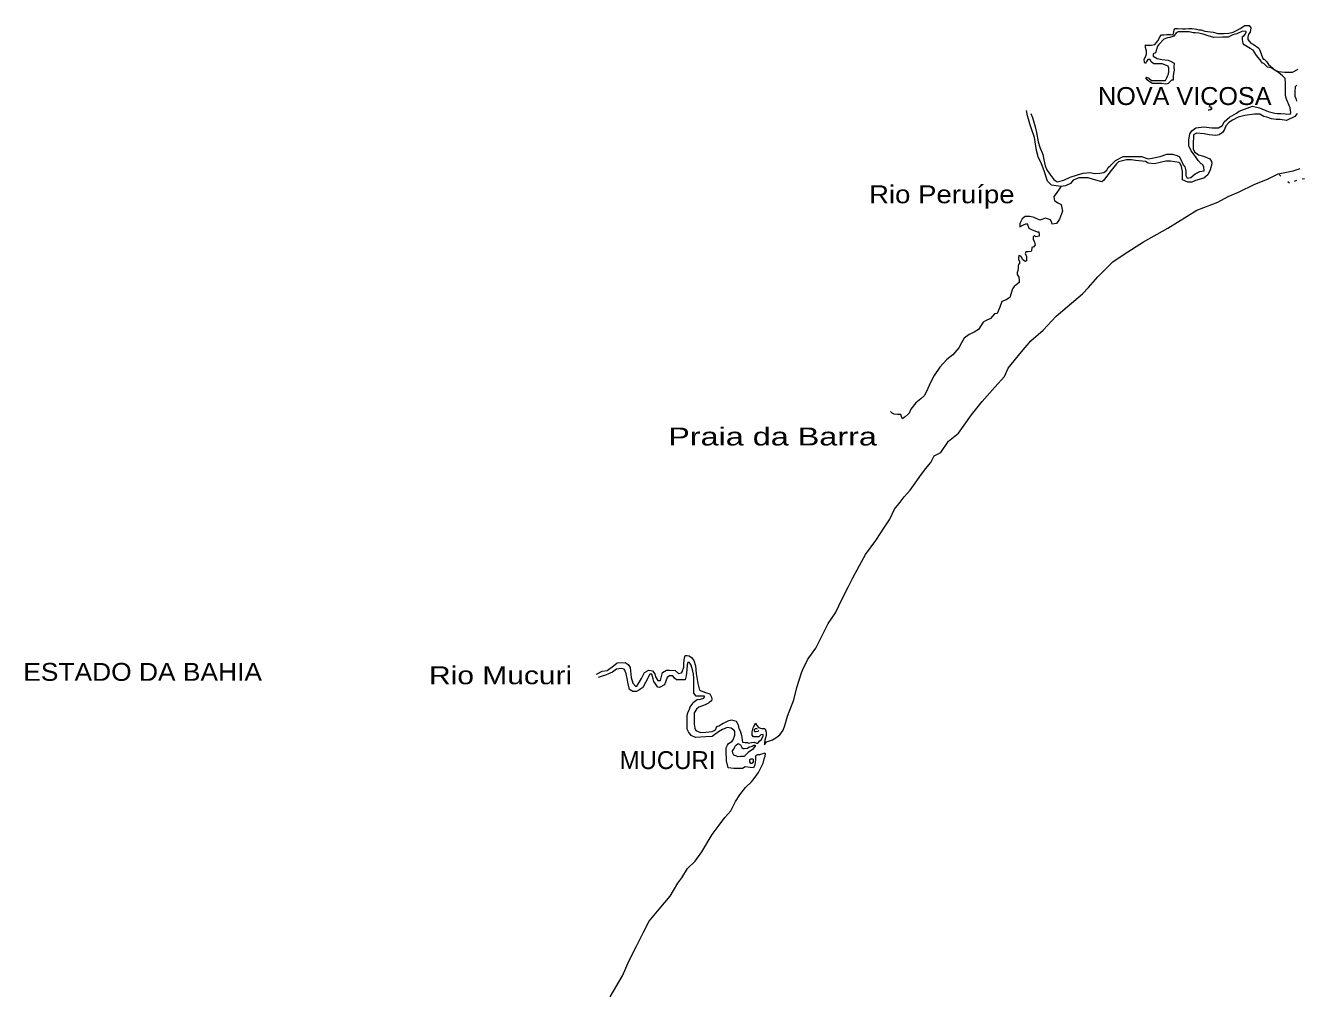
# Model space of a CAD drawing. Extents: x 47169 to 972804, y 7447977 to 9608469.
# Drawn here: x 414694 to 460779, y 7990522 to 8025478 of the extents above; entities that cross this region are included whole.
import ezdxf

# ---------------------------------------------------------------- set-up
doc = ezdxf.new("R2010")
doc.units = 0
doc.header["$LTSCALE"] = 270
doc.linetypes.add('DOTTED', pattern=[1.5, 0.3, -1.2])
doc.layers.add('1', color=7, linetype='Continuous', lineweight=13)
doc.layers.add('3', color=7, linetype='Continuous')

msp = doc.modelspace()

# ---------------------------------------------------------------- linework, layer by layer
at = {"layer": '1'}
for points in [[(456210.3, 8025144.1), (456302.5, 8025136.6), (456333, 8025245.1), (456341.3, 8025321.4), (456371.9, 8025360.2), (456464.1, 8025368.2), (456641, 8025359.7), (456748, 8025352.2), (456870.9, 8025368), (456993.9, 8025360.5), (457147.5, 8025337.6), (457232.3, 8025322.3), (457324.5, 8025322.5), (457447.5, 8025268.5), (457755.9, 8025238.2), (457931.9, 8025184.4), (458155.5, 8025184.9), (458323.9, 8025191.8), (458478.5, 8025230.9), (458623.5, 8025307.5), (458731.5, 8025362), (458900.8, 8025477.4), (458915.6, 8025477.4), (459061.8, 8025477.7), (459116, 8025384.9), (459093, 8025238.8), (459031.7, 8025162.3), (459016.1, 8025055), (459008.9, 8024962), (459124.6, 8024839.5), (459208.4, 8024793.2), (459416.3, 8024655.3), (459463.2, 8024539.2), (459547.4, 8024309.3), (459570.8, 8024255.1), (459601.5, 8024255.2), (459693.9, 8024170.2), (459763, 8024055.2)], [(459594.4, 8024093.6), (459540.4, 8024109), (459462.8, 8024231.6), (459324.7, 8024392.9), (459201.4, 8024577.4), (459093.2, 8024646.9), (458877.9, 8024770.4), (458839.6, 8024823.4), (458817.1, 8024969.4), (458824.3, 8025077.8), (458878.2, 8025115.5), (458923.6, 8025177.6), (458946.8, 8025231.9), (458946.8, 8025261.7), (458823.9, 8025269.2), (458609, 8025169.2), (458462.8, 8025131.3), (458302, 8025053.5), (458094.3, 8025054.2), (457778.6, 8025038), (457579.3, 8025099.5), (457386.3, 8025161.1), (457240, 8025191.7), (457102.2, 8025206.9), (457024.9, 8025214.5), (456887.1, 8025245.2), (456755.7, 8025244.9), (456602.1, 8025244.6), (456486.6, 8025244.3), (456417.8, 8025206.5), (456333.3, 8025083.5), (456187.2, 8025036.8), (456095, 8025028.8), (455964.8, 8024975.4), (455788.3, 8024790.2), (455734.4, 8024721.5), (455666.1, 8024482.4), (455581.4, 8024451.2), (455581.6, 8024367.1), (455728, 8024274.5), (455889.1, 8024243.9), (456119.1, 8024213.5), (456234.7, 8024175), (456335.5, 8024114.4), (456334.7, 8023968.3), (456335, 8023852.1), (456313, 8023729.3), (456304.7, 8023652.9), (456304.9, 8023567.7), (456305, 8023491.4), (456243.6, 8023491.2), (456151.6, 8023398.1), (456128.4, 8023368.2), (456036.2, 8023352.5), (455882.6, 8023367.6), (455721.6, 8023367.3), (455651.7, 8023367.1), (455544.7, 8023366.9), (455490.5, 8023413.2), (455429, 8023444.1), (455367.4, 8023505.9), (455313.2, 8023582.1), (455336.5, 8023605.4), (455421.3, 8023566.9), (455521.1, 8023483), (455598.4, 8023482.1), (455698, 8023482.3), (455844.2, 8023482.6), (456028.5, 8023483), (456073.9, 8023575), (456097.1, 8023637), (456136.1, 8023713.4), (456143.3, 8023821.8), (456150.5, 8023929.2), (456119.5, 8024006.5), (455904.3, 8024082.4), (455720, 8024083.1), (455604.5, 8024082.9), (455512.1, 8024159), (455489.8, 8024205.4), (455450.5, 8024236.3), (455389, 8024243.9), (455343.7, 8024166.4), (455297.2, 8024097.7), (455266.4, 8024136.3), (455251.3, 8024259.1), (455327.3, 8024389.8), (455335.6, 8024451.8), (455335.4, 8024543.6), (455304.4, 8024674.1), (455296.7, 8024774.8), (455334.9, 8024767.1), (455511.8, 8024766.4), (455642.1, 8024789.9), (455757.3, 8024936.2), (455818.4, 8025059.2), (455879.7, 8025136.8), (455964.5, 8025137), (456080, 8025143.8), (456148.8, 8025144), (456210.3, 8025144.1)], [(460088.6, 8022286.8), (460096, 8022286.8), (460211.5, 8022279.3), (460372.5, 8022271.9), (460549.5, 8022263.4), (460572.7, 8022317.6), (460541.6, 8022494.6), (460410.7, 8022809.6), (460379.7, 8022932.4), (460371.3, 8023401.5), (460363.6, 8023555.3), (460263.8, 8023648), (460124.8, 8023770.5), (459855.4, 8023940.4), (459725, 8023963.3), (459594.4, 8024093.6)], [(459763, 8024055.2), (460001.7, 8023855.5), (460124.7, 8023801.5), (460355.8, 8023778.7), (460540.1, 8023779.1), (460632.2, 8023779.3), (460832.3, 8023887)], [(460786.8, 8023309.4), (460725.5, 8023248.4), (460717.3, 8023086.9), (460717.7, 8022909.8), (460748.6, 8022833.5), (460779.5, 8022732.9)], [(451142.2, 8022285.5), (451204, 8022139.6), (451250, 8021970.4), (451304.4, 8021801.3), (451350.5, 8021593.4), (451412.7, 8021262.7), (451474.7, 8021063.7), (451582.3, 8020794), (451620.9, 8020609.4), (451668, 8020387.1), (451721.4, 8020240.1), (451829.8, 8020086.5), (451983.9, 8019886.7), (452099.5, 8019810.6), (452345.1, 8019864.3), (452567.3, 8019972.2), (452836.2, 8020056.9), (453036.2, 8020119.3), (453289.3, 8020149.8), (453458.9, 8020111.5), (453650.6, 8020119.7), (453789.3, 8020151), (453897.1, 8020235.3), (453942.5, 8020327.2), (454019.7, 8020381.7), (454219.4, 8020581.3), (454488.1, 8020720.2), (454772, 8020728.6), (455064.4, 8020728.1), (455156.5, 8020728.4), (455402.5, 8020644.8), (455548.6, 8020659.5), (455832.4, 8020722.1), (456070.5, 8020806.8), (456278.1, 8020815), (456439.2, 8020761.1), (456524.1, 8020722.6), (456585.8, 8020614.3), (456670.9, 8020423), (456725.1, 8020345.7), (456763.5, 8020207.5), (456763.9, 8020038.2), (456817.1, 8019945.4), (456948.4, 8019961.2), (457101.7, 8020092.1), (457271, 8020176.5), (457424.5, 8020207.8), (457416.8, 8020346.1), (457362.6, 8020431.2), (457315.9, 8020462.1), (457216.1, 8020584.7), (457116.2, 8020730.5), (456962.2, 8020930.4), (456877, 8021115), (456876.6, 8021323), (456907.9, 8021553.2), (456983.9, 8021660.7), (457129.9, 8021761.7), (457414.7, 8021799.9), (457706.1, 8021769.6), (457951.9, 8021762.3), (458097.9, 8021854.5), (458159.1, 8021977.4), (458351.5, 8022154.9), (458604.4, 8022292.6), (458697.5, 8022370.2), (459181.2, 8022547.1), (459434.5, 8022493.5), (459750.5, 8022355.8), (459996.4, 8022302.1), (460088.6, 8022286.8)], [(460181.2, 8022071.2), (460035, 8022063.2), (459865.5, 8022093.8), (459696.9, 8022147.7), (459596.2, 8022178.5), (459442.4, 8022263.3), (459250.7, 8022262.9), (458897, 8022216.9), (458666.2, 8022146.7), (458451.3, 8022038.9), (458328.6, 8021962.3), (458213.4, 8021839.2), (458159.7, 8021700.8), (458098.4, 8021600), (457968.3, 8021515.7), (457852.9, 8021492.2), (457614.5, 8021516), (457422.7, 8021546.6), (457153.6, 8021569.2), (457045.7, 8021507), (457030.6, 8021146.3), (457030.9, 8021006.9), (457077.7, 8020891.9), (457223.1, 8020784.9), (457400.1, 8020738.9), (457631.2, 8020638.7), (457700.3, 8020547), (457700.5, 8020454), (457646.9, 8020239.3), (457562.5, 8020062.1), (457416.6, 8019939), (457117, 8019854.2), (456986.9, 8019792), (456833.3, 8019791.7), (456648.8, 8019876.4), (456640.7, 8020176.2), (456609.6, 8020361), (456562.8, 8020475.9), (456517.1, 8020506.8), (456209.9, 8020552.6), (456040.4, 8020552.2), (455832.8, 8020506.4), (455625.3, 8020460.6), (455395.4, 8020483.3), (455303.1, 8020543.9), (454941.8, 8020582.9), (454795.6, 8020605.8), (454618.7, 8020605.4), (454319.1, 8020536.1), (454250.4, 8020458.5), (454058.2, 8020220.2), (453774.1, 8019857.8), (453712.7, 8019812.2), (453412.8, 8019889), (453228.3, 8019950.5), (452890.4, 8019949.7), (452683, 8019865.1), (452583.7, 8019749.8), (452407, 8019664.2), (452230.2, 8019633.9), (451892.2, 8019687.3), (451745.7, 8019825.2), (451629.3, 8020202.2), (451529.1, 8020455.4), (451405.6, 8020717.3), (451352.1, 8020939.5), (451274.6, 8021409.5), (451173.2, 8021724.6), (451103.9, 8021909.2), (451065.4, 8022078.4), (451019.5, 8022201.1), (450988.3, 8022393.5)], [(460802.6, 8022279.4), (460719.1, 8022179.6), (460411.2, 8022033), (460181.2, 8022071.2)], [(457924.8, 8019070.4), (458301.5, 8019270.4), (458669.7, 8019431.6), (459269.7, 8019724.9), (459722.7, 8019909.5), (460114.2, 8020095.1), (460659.5, 8020210.1), (460905.1, 8020294.7)], [(452230.2, 8019633.9), (452199.6, 8019579.6), (452068.8, 8019379), (451984.3, 8019279.2), (451984.5, 8019179.7), (452008, 8019125.5), (452123.6, 8019049.5), (452246.6, 8018987.8), (452292.7, 8018748.9), (452178, 8018448.8), (452071.4, 8018294.8), (451916.8, 8018272.3), (451901.9, 8018325.3), (451856.1, 8018433.6), (451670.6, 8018495.2), (451471.6, 8018417.2), (451271.2, 8018517.4), (451110.1, 8018548), (450933.2, 8018547.5), (450825.4, 8018463.2), (450756.9, 8018324.7), (450749.6, 8018278.2), (450749.8, 8018200.8), (450749.9, 8018170.9), (450849.3, 8018239.8), (450987.9, 8018302), (451041, 8018240.2), (451072, 8018125.2), (451164.2, 8018079), (451372, 8017994.3), (451433.5, 8017994.5), (451449.6, 8017887.2), (451449.8, 8017840.7), (451325.9, 8017817.2), (451272.8, 8017863.5), (451226.3, 8017816.9), (451234, 8017725.1), (451280.8, 8017624.5), (451295.9, 8017517.3), (451258, 8017448.6), (451180.7, 8017425.2), (451173.6, 8017302.3), (451157.8, 8017279), (451043.4, 8017263.3), (450958.7, 8017263.1), (450935.5, 8017202.2), (450981.3, 8017109.3), (450981.7, 8016947.8), (450936.2, 8016916.7), (450843.9, 8016986.2), (450813, 8017063.5), (450782.2, 8017116.6), (450704.8, 8017139.6), (450697.6, 8017055.5), (450697.8, 8016978.1), (450728.6, 8016925), (450728.9, 8016839.9), (450698.2, 8016816.5), (450691, 8016747.9), (450690.1, 8016670.5), (450668, 8016594.1), (450652.4, 8016508.8), (450652.5, 8016448), (450706.8, 8016355.2), (450721.9, 8016232.4), (450722.1, 8016155), (450538.2, 8016016.2), (450484.4, 8015924.2), (450384.6, 8015608.7), (450247.1, 8015524.2), (450093.7, 8015463), (450016.9, 8015262.5), (449925.3, 8015038.8), (449833.2, 8015024.2), (449687.6, 8014846.8), (449503.5, 8014762.2), (449410.5, 8014715.5), (449242.7, 8014454), (449088.4, 8014361.7), (448912.8, 8014276.1), (448727.8, 8014145), (448636.2, 8013968.9), (448537.1, 8013783.9), (448314.3, 8013537.7), (448099.8, 8013367.8), (447846.4, 8013082.8), (447639.7, 8012782.4), (447524.9, 8012552), (447349, 8012181.9), (447272.1, 8012051.2), (447157, 8011935.8), (446973.2, 8011789.3), (446789.5, 8011566.4), (446728.5, 8011420.2), (446697.9, 8011389.1), (446590.2, 8011289.2), (446552.1, 8011258.1), (446490.8, 8011219.2), (446459.9, 8011304.4), (446436.4, 8011366.3), (446313.6, 8011365.9)], [(439764.7, 8000056.8), (439833.4, 8000080.3), (439986.6, 8000180.3), (440047.9, 8000210.4), (440170.4, 8000265), (440293.1, 8000296.4), (440462.5, 8000258.1), (440531.7, 8000118.9), (440562.8, 7999988.5), (440601.2, 7999896.8), (440624.7, 7999819.4), (440655.7, 7999735.4), (440663.3, 7999658), (440679.4, 7999581.7), (440694.5, 7999488.8), (440786.6, 7999481.3), (440871.3, 7999473.8), (440902, 7999458.4), (441017.3, 7999482), (441116.7, 7999490), (441201.5, 7999451.6), (441247, 7999451.7), (441324, 7999543.8), (441370.4, 7999574.9), (441438.8, 7999713.4), (441438.6, 7999775.4), (441354, 7999759.6), (441278, 7999689.7), (441146.8, 7999682.7), (441085.4, 7999682.5), (441047.2, 7999743.2), (441039.4, 7999866), (441077, 8000005.5), (441100.2, 8000058.7), (441168.6, 8000181.7), (441208, 8000097.8), (441277, 8000028.2), (441384, 7999989.9), (441438, 7999990), (441499.3, 7999990.2), (441530.2, 7999943.8), (441553.7, 7999852), (441554.1, 7999729.2), (441500.6, 7999567.5), (441492.5, 7999452.4), (441492.7, 7999390.5), (441562.1, 7999505.8), (441776.8, 7999575), (441899.3, 7999652.8), (442045, 7999752.8), (442159.8, 7999930.2), (442228.1, 8000091.9), (442320.2, 8000429.7), (442549.2, 8001022.3), (442663.2, 8001476.3), (442831, 8002000.1), (442877.2, 8002130.8), (443044.4, 8002477.6), (443098.2, 8002554.1), (443343.8, 8002901.1), (443480.6, 8003170.4), (443794.2, 8003793.1), (444063, 8004178.9), (444299.7, 8004686.3), (444529.1, 8005140.6), (444689.2, 8005448.7), (444927.1, 8005895.2), (445148.3, 8006295.3), (445523.7, 8006803.1), (445845.2, 8007280.8), (446029.7, 8007573.4), (446197, 8007935.7), (446412.3, 8008189.7), (446550.4, 8008381.5), (446764.7, 8008628.8), (447016.8, 8008966.9), (447124.4, 8009121), (447331.1, 8009398.2), (447515.7, 8009636.5), (447645.3, 8009868.1), (447875.8, 8009999.3), (448159.5, 8010399.4), (448527.2, 8010699.1), (448994.5, 8011354.2), (449385, 8011838.8), (449837.9, 8012362.2), (450190.6, 8012754.7), (450328.5, 8013054.9), (450803.5, 8013648), (451140.4, 8014048.3), (451593.7, 8014433.3), (452061.6, 8014934.6), (453020.1, 8015750.1), (453234.6, 8015981.9), (453572.6, 8016358.8), (454116.7, 8016905.6), (454531.2, 8017182), (455230.3, 8017637.2), (456113.5, 8018130.5), (457164.9, 8018784.5), (457924.8, 8019070.4)], [(446313.6, 8011365.9), (446190.7, 8011388.8), (446121.8, 8011419.6), (446051.8, 8011480.3)], [(435398.6, 8001955.9), (435605.7, 8002063.9), (435789.8, 8002087.8), (436012.5, 8002256.7), (436142.3, 8002372.2), (436441.8, 8002380.9), (436541.5, 8002311.5), (436619.1, 8002204.5), (436658.4, 8001835), (436712, 8001634.9), (436812.9, 8001520.2), (436865.8, 8001528.1), (437026.8, 8001805.2), (437141.5, 8002020.3), (437294.7, 8002098.2), (437433.4, 8002075.4), (437509.9, 8001967.2), (437541, 8001860), (437626.1, 8001722), (437718.1, 8001722.3), (437755.8, 8001868.4), (437794.5, 8002014.6), (437931.8, 8002099.1), (438047.1, 8002099.5), (438254.6, 8002092.4), (438370.3, 8001976.6), (438477.1, 8002000.2), (438507.7, 8002039), (438561.1, 8002208.4), (438569.1, 8002362.3), (438591.8, 8002546), (438613.8, 8002631.3), (438683.6, 8002631.5), (438752.4, 8002624), (438844.7, 8002562.3), (438929.7, 8002447.5), (438991.7, 8002262.9), (439014.8, 8001978.6), (439069.9, 8001624.7), (439132, 8001378.2), (439354.5, 8001293.7), (439500.7, 8001241), (439569.9, 8001125.1), (439584.9, 8001056.5), (439562.9, 8000994.5), (439478.4, 8000925.6), (439462.6, 8000910.1), (439363.3, 8000863.3), (439271.4, 8000817.7), (439109.6, 8000755.2), (439026.2, 8000694.1), (438933.5, 8000555.5), (438933.9, 8000439.3), (438934.8, 8000147.2), (438966, 8000001.2), (438996.9, 7999909.5), (439165.4, 7999840.3), (439358, 7999848.7), (439596, 7999879.3), (439711.1, 7999933.9), (439764.7, 8000056.8)], [(439818.2, 7999872.2), (439588.1, 7999694.5), (439358.5, 7999679.4), (438990.3, 7999662.8), (438828.2, 7999732), (438728.3, 7999862.2), (438682.5, 7999962.7), (438681.9, 8000146.4), (438680.9, 8000469.5), (438711.3, 8000554.8), (438772.2, 8000693.3), (438787.9, 8000777.4), (438849, 8000847.3), (438902.7, 8000931.6), (439048.4, 8001039.4), (439162.7, 8001047.5), (439285.3, 8001086.6), (439308.4, 8001147.5), (439316.9, 8001163), (439116.9, 8001155.7), (439008.9, 8001155.4), (438932.4, 8001270.2), (438931.8, 8001455), (438923.3, 8001809), (438915.4, 8001962.8), (438891.8, 8002062.3), (438853.3, 8002192.8), (438829.7, 8002285.6), (438784, 8002354.1), (438768, 8002377.3), (438706.7, 8002377.1), (438683.6, 8002292.9), (438676.8, 8002115.9), (438654.2, 8001900), (438616.5, 8001753.9), (438555.2, 8001747), (438301.2, 8001746.2), (438224.8, 8001808), (438163.2, 8001891.9), (438040.4, 8001899.2), (437963.3, 8001838.1), (437864.7, 8001567.8), (437679.8, 8001475.4), (437626.8, 8001483), (437480.1, 8001690.5), (437449.1, 8001783.4), (437403.1, 8001952.5), (437325.8, 8001952.2), (437173.3, 8001659.7), (437073.4, 8001474.6), (436936.1, 8001382.3), (436844.2, 8001327.8), (436713, 8001327.3), (436590, 8001404.4), (436543.8, 8001604.5), (436512.5, 8001804.7), (436473.9, 8001966.1), (436426.8, 8002104.2), (436396, 8002142.9), (436289, 8002165.8), (436119.8, 8002134.2), (435974.1, 8002034.2), (435836.7, 8001971.8), (435728.9, 8001926), (435598.9, 8001886.9), (435460.4, 8001833.3)], [(435896.4, 7990257.9), (436340.3, 7991020.6), (436583.9, 7991574.6), (436843.5, 7992090), (437103.1, 7992598.7), (437309.1, 7992998.8), (437730.6, 7993506.9), (438074.2, 7993908.5), (438349.9, 7994385.2), (438495.3, 7994570.4), (438701.5, 7994916.3), (438969.4, 7995178.2), (439214.9, 7995517.6), (439596.9, 7996149.5), (439841.4, 7996487.7), (440047.9, 7996764.9), (440270.4, 7997003.5), (440438.7, 7997334.8), (440591.3, 7997580.9), (440797.9, 7997850.4), (441020.5, 7998051.4), (441150.1, 7998228.8), (441272.4, 7998390.7), (441356.5, 7998566.9), (441440.7, 7998736.4), (441479.4, 7998882.6), (441509.7, 7998990), (441524.3, 7999067.5), (441501, 7999090.7), (441470.3, 7999082.8), (441309.6, 7999028.1), (441233.4, 7999029), (441163.7, 7998997.8), (441156.5, 7998935.8), (441156.7, 7998867.2), (441141.4, 7998674.7), (441087.7, 7998567.2), (440965, 7998574.5), (440788.2, 7998597.2), (440688.9, 7998542.7), (440374.7, 7998535.1), (440167.2, 7998565.5), (440112.4, 7998818.7), (440112.1, 7998926), (440104.2, 7999080.9), (440103.9, 7999196), (440103.8, 7999226.9), (440103.6, 7999287.8), (440142.4, 7999388.6), (440180.4, 7999441.8), (440310.3, 7999519.7), (440356.7, 7999572.9), (440417.5, 7999750.2), (440417.2, 7999849.7), (440409.7, 7999872.9), (440386.3, 7999911.6), (440279.2, 8000004.2), (440133.1, 8000019.2), (439964, 7999956.8), (439818.2, 7999872.2)], [(441277.3, 7999913.2), (441246.8, 7999874.4), (441185.4, 7999866.4), (441138.9, 7999866.3), (441131.3, 7999905), (441131.2, 7999959.2), (441138.5, 7999967), (441161.8, 7999990.3), (441192.4, 7999990.4), (441207.3, 7999990.4), (441215.8, 7999959.5)], [(441079.7, 7998781.8), (441025.9, 7998713), (440987.9, 7998712.9), (440957, 7998773.7), (440956.7, 7998851.1), (440956.7, 7998866.6), (440987.3, 7998882.2), (441010.6, 7998882.3), (441048.7, 7998882.4), (441072, 7998874.7), (441079.5, 7998843.8), (441079.6, 7998812.8), (441079.8, 7998750.8)]]:
    msp.add_lwpolyline(points, dxfattribs=at)
at = {"layer": '1', "linetype": 'DOTTED'}
msp.add_lwpolyline([(462121.4, 8020702), (462210.5, 8020639.1), (462361.1, 8020514.4), (462261.9, 8020371.5), (462198.4, 8020308.3), (462066.4, 8020100), (461687.5, 8019956.6), (461342.2, 8019938.2), (461062.6, 8019917.7), (460770.4, 8019850.8), (460523.8, 8019758.4), (460114.2, 8020095.1)], dxfattribs=at)
at = {"layer": '1'}
msp.add_lwpolyline([(440671.8, 7999303.9), (440718.5, 7999266.4), (440749.1, 7999266.5), (440871.9, 7999273.5), (440925.7, 7999304.7), (441039.9, 7999351.5), (441101.2, 7999381.6), (441147.7, 7999381.7), (441147.8, 7999351.8), (441056.1, 7999227.6), (440894.5, 7999119.8), (440749, 7998973.3), (440656.9, 7998966.4), (440618.8, 7998966.3), (440510.9, 7998966), (440480.2, 7998989.1), (440373.2, 7999019.8), (440334.9, 7999088.2), (440327.2, 7999173.4), (440372.5, 7999242.2), (440418.8, 7999319.7), (440440.9, 7999365.2), (440472.6, 7999396.2), (440525.4, 7999427.4), (440533.8, 7999442.9), (440617.5, 7999396.7)], close=True, dxfattribs=at)

# ---------------------------------------------------------------- texts
at = {"layer": '3'}
for s, height, width, p in [('NOVA VIÇOSA', 650.2, 1.05, (453580.8, 8022592.2)), ('Rio Peruípe', 650.1, 1.15, (445277.7, 8019029.6)), ('Praia da Barra', 649.8, 1.35, (437998.5, 8010248.7)), ('ESTADO DA BAHIA', 649.6, 1.1, (414615.3, 8001715.9)), ('Rio Mucuri', 649.6, 1.25, (429326.7, 8001592.2))]:
    msp.add_text(s, height=height, dxfattribs=dict(at, width=width)).set_placement(p)
msp.add_text('MUCURI', height=649.5, dxfattribs=at).set_placement((436235.7, 7998516))

doc.saveas('drawing.dxf')
